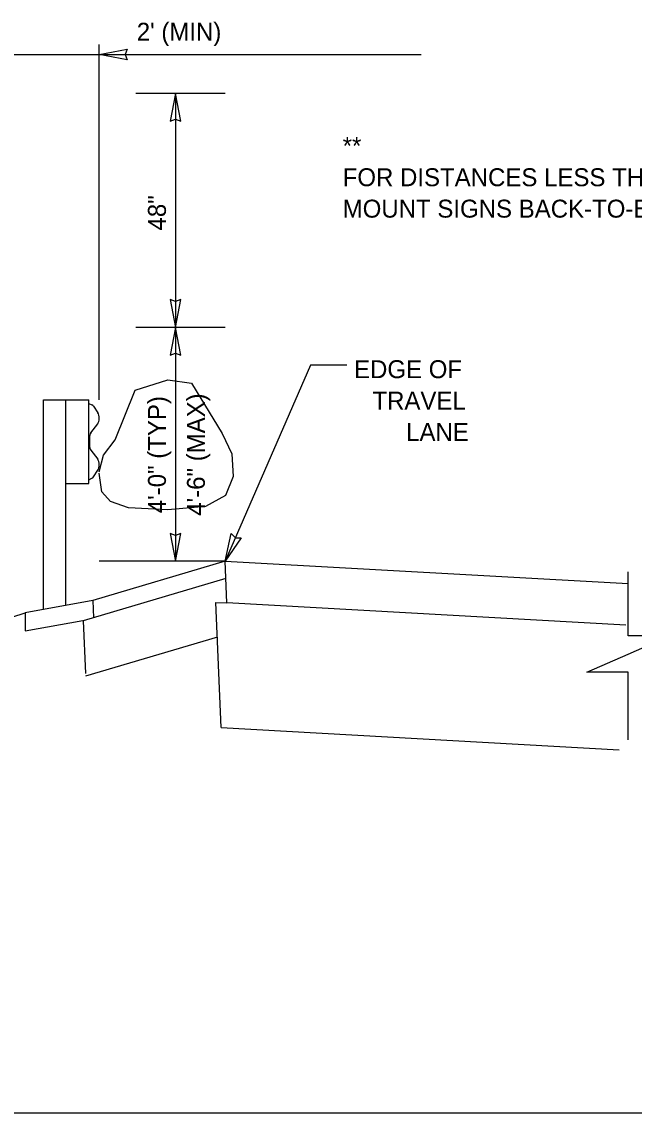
# Model space of a CAD drawing. Extents: x 57428 to 58066, y 11696 to 12105.
# Drawn here: x 57796 to 57891.5, y 11934.3 to 12104.5 of the extents above; entities that cross this region are included whole.
import ezdxf

# ---------------------------------------------------------------- set-up
doc = ezdxf.new("R2010")
doc.units = 0
for name, color, linetype in [('52', 7, 'Continuous'), ('62', 7, 'Continuous'), ('Default', 7, 'Continuous'), ('DimLines_dp', 7, 'Continuous'), ('TextMisc', 7, 'Continuous'), ('XSGrdLine_ex', 7, 'Continuous')]:
    doc.layers.add(name, color=color, linetype=linetype)

msp = doc.modelspace()

# ---------------------------------------------------------------- linework, layer by layer
at = {"layer": '52'}
msp.add_line((57827.72, 12020.37), (57808.08, 12020.37), dxfattribs=at)
at = {"layer": '62'}
msp.add_lwpolyline([(57808.06, 12034.31), (57808.76, 12036.91), (57810.56, 12039.32), (57813.66, 12047.07), (57818.77, 12048.67), (57822.47, 12048.17), (57827.27, 12040.32), (57828.77, 12037.11), (57828.97, 12033.61), (57827.77, 12030.61), (57824.67, 12028.9), (57818.77, 12028.4), (57812.66, 12028.7), (57809.86, 12029.7), (57808.46, 12031.21), (57808.06, 12034.11)], dxfattribs=at)
at = {"layer": 'Default'}
msp.add_lwpolyline([(57890.6, 11992.52), (57890.6, 12003.08), (57884.14, 12003.08), (57890.6, 12005.89), (57897.06, 12008.71), (57890.6, 12008.71), (57890.6, 12018.71)], dxfattribs=at)
at = {"layer": 'DimLines_dp'}
for p, q in [((57808.08, 12045.58), (57808.08, 12100.98)), ((57788.75, 12099.43), (57858.29, 12099.43)), ((57808.08, 12099.43), (57812.43, 12100.27)), ((57812.43, 12098.62), (57808.08, 12099.43)), ((57812.43, 12100.27), (57812.1, 12099.43)), ((57812.1, 12099.43), (57812.43, 12098.62)), ((57827.72, 12093.37), (57813.79, 12093.37)), ((57819.97, 12093.37), (57819.13, 12089.02)), ((57819.97, 12093.37), (57819.97, 12056.87)), ((57820.78, 12089.02), (57819.97, 12093.37)), ((57819.13, 12089.02), (57819.97, 12089.35)), ((57819.97, 12089.35), (57820.78, 12089.02)), ((57819.97, 12060.89), (57819.16, 12061.22)), ((57819.16, 12061.22), (57819.97, 12056.87)), ((57819.97, 12060.89), (57819.16, 12061.22)), ((57819.16, 12061.22), (57819.97, 12056.87)), ((57819.97, 12056.87), (57820.81, 12061.22)), ((57820.81, 12061.22), (57819.97, 12060.89)), ((57819.97, 12056.87), (57820.81, 12061.22)), ((57820.81, 12061.22), (57819.97, 12060.89)), ((57827.72, 12056.87), (57813.79, 12056.87)), ((57819.97, 12056.87), (57819.13, 12052.52)), ((57819.97, 12056.87), (57819.97, 12020.37)), ((57820.78, 12052.52), (57819.97, 12056.87)), ((57819.13, 12052.52), (57819.97, 12052.85)), ((57819.97, 12052.85), (57820.78, 12052.52)), ((57841.04, 12050.98), (57827.72, 12020.37)), ((57846.68, 12050.98), (57841.04, 12050.98)), ((57819.97, 12024.39), (57819.16, 12024.72)), ((57819.16, 12024.72), (57819.97, 12020.37)), ((57819.97, 12020.37), (57820.81, 12024.72)), ((57820.81, 12024.72), (57819.97, 12024.39)), ((57827.72, 12020.37), (57828.68, 12024.69)), ((57830.19, 12024.03), (57827.72, 12020.37)), ((57828.68, 12024.69), (57829.32, 12024.05)), ((57829.32, 12024.05), (57830.19, 12024.03))]:
    msp.add_line(p, q, dxfattribs=at)
at = {"layer": 'TextMisc'}
msp.add_line((58065.89, 11934.25), (57709.55, 11934.25), dxfattribs=at)
at = {"layer": 'XSGrdLine_ex'}
for p, q in [((57799.36, 12012.84), (57799.36, 12045.58)), ((57799.36, 12045.58), (57806.46, 12045.58)), ((57802.86, 12013.47), (57802.86, 12045.58)), ((57806.46, 12032.49), (57806.46, 12045.58)), ((57806.47, 12045.01), (57806.94, 12044.78)), ((57807.17, 12044.57), (57807.87, 12043.53)), ((57806.76, 12040.42), (57807.84, 12041.82)), ((57806.54, 12039.6), (57806.54, 12038.5)), ((57806.76, 12037.7), (57807.84, 12036.29)), ((57807.17, 12033.54), (57807.87, 12034.57)), ((57802.86, 12032.49), (57806.46, 12032.49)), ((57806.47, 12033.1), (57806.94, 12033.31)), ((57827.72, 12020.37), (57807.08, 12014.23)), ((57828, 12013.86), (57827.72, 12020.37)), ((57827.72, 12020.37), (57890.6, 12016.89)), ((57827.83, 12017.7), (57805.55, 12011.07)), ((57807.08, 12014.23), (57796.52, 12012.33)), ((57807.08, 12014.23), (57807.2, 12011.56)), ((57826.26, 12013.95), (57828, 12013.86)), ((57827.12, 11994.41), (57826.26, 12013.95)), ((57890.24, 12010.41), (57828, 12013.86)), ((57751.86, 11997.83), (57796.52, 12012.33)), ((57796.52, 12012.33), (57796.52, 12009.5)), ((57796.52, 12009.5), (57805.54, 12011.12)), ((57805.55, 12011.07), (57805.91, 12002.85)), ((57826.5, 12008.55), (57805.93, 12002.43)), ((57827.12, 11994.41), (57889.16, 11990.97))]:
    msp.add_line(p, q, dxfattribs=at)
for centre, major_axis, start_param, end_param in [((57806.79, 12043.53), (0, 1.28), 5.646537, 6.041895), ((57807.55, 12042.69), (0, -1.05), 0.577206, 2.505315), ((57807.03, 12039.59), (0, -0.976), 3.718758, 4.701029), ((57807.03, 12038.51), (0, -0.976), 4.723749, 5.70602), ((57807.55, 12035.41), (0, 1.05), 3.777871, 5.70598), ((57806.79, 12034.56), (0, -1.28), 0.24129, 0.636649)]:
    msp.add_ellipse(centre, major_axis=major_axis, ratio=0.5, start_param=start_param, end_param=end_param, dxfattribs=at)

# ---------------------------------------------------------------- texts
at = {"layer": 'DimLines_dp'}
for s, p in [("2' (MIN)", (57813.93, 12101.59)), ('**', (57846.05, 12083.79)), ("FOR DISTANCES LESS THAN 9',", (57846.05, 12078.89)), ('MOUNT SIGNS BACK-TO-BACK', (57846.05, 12073.99)), ('EDGE OF ', (57847.82, 12048.94)), ('TRAVEL ', (57850.69, 12044.04)), ('LANE', (57855.95, 12039.14))]:
    msp.add_text(s, height=2.8, dxfattribs=at).set_placement(p)
for s, p in [('48"', (57818.48, 12071.98)), ('4\'-6" (MAX)', (57824.56, 12027.47)), ('4\'-0" (TYP)', (57818.48, 12027.87))]:
    msp.add_text(s, height=2.8, rotation=90, dxfattribs=at).set_placement(p)

doc.saveas('drawing.dxf')
